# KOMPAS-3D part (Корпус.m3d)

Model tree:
1. Эскиз:1
2. Эскиз:2
3. Кинематическая операция:1
4. Зеркальный массив:1  (with: Кинематическая операция:1)  (labels: Экземпляр ( 1 ); Экземпляр ( 2 ))
5. Смещенная плоскость:1
     Расстояние = 9
6. Эскиз:3
7. Спираль цилиндрическая:1
     Число витков = 95; Шаг = 0.184211; Высота = 17.5; Диаметр 1 = 0.1; Диаметр 2 = 10
8. Перпендикулярная плоскость:1
9. Эскиз:4
10. Кинематическая операция:2
11. Эскиз:5
12. Поверхность вращения:1
     Угол 1 = 360; Угол 2 = 360
13. Придать толщину:1
     Толщина стенки 1 = 0.1
14. Вырезать элемент выдавливания:2
     Расстояние 1 = 0.1

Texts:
  Экземпляр ( 1 )
  Экземпляр ( 2 )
